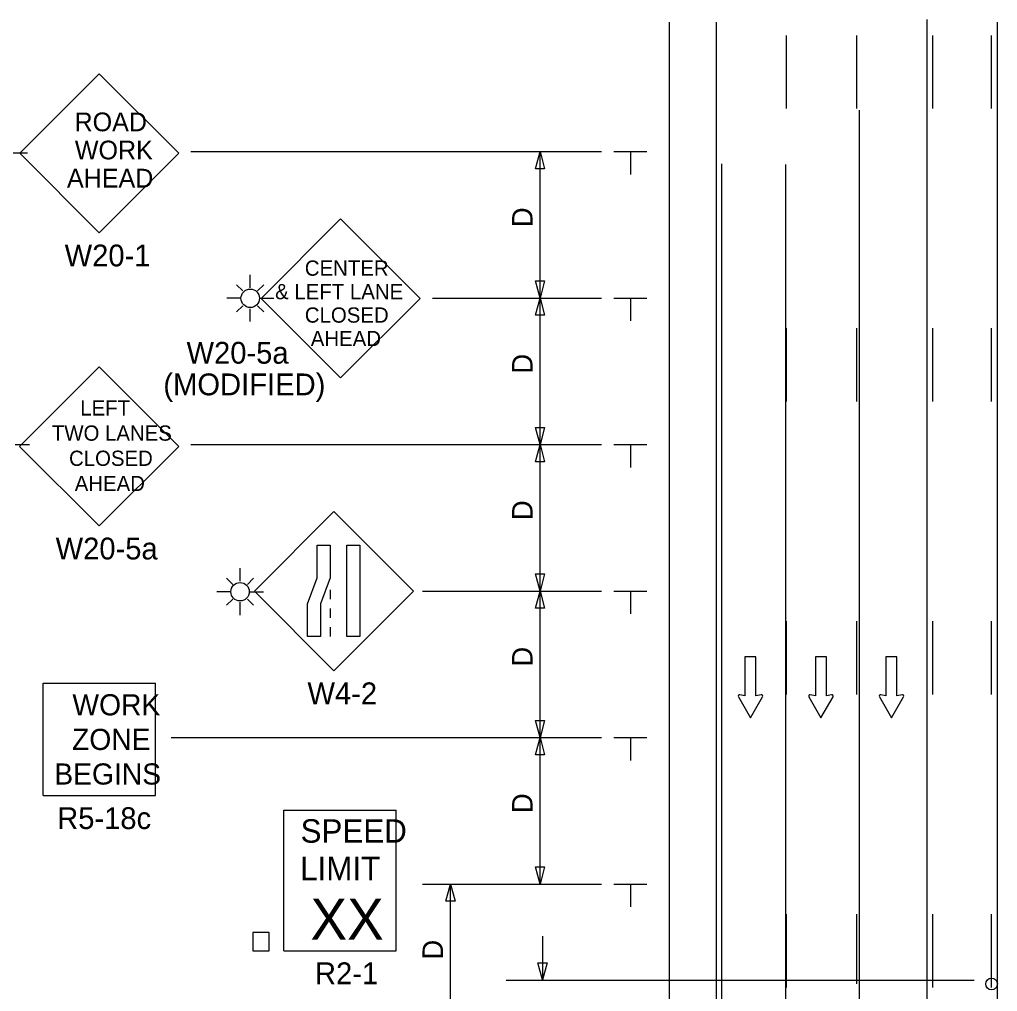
# Model space of a CAD drawing. Extents: x 16038 to 19504, y 5920 to 8321.
# Drawn here: x 16748.5 to 17082.4, y 7879.9 to 8211.6 of the extents above; entities that cross this region are included whole.
import ezdxf

# ---------------------------------------------------------------- set-up
doc = ezdxf.new("R2010")
doc.units = 0
for name, color, linetype in [('ALI_LEGAL_EX', 7, 'Continuous'), ('MT_SCRATCH_LEVEL_E', 7, 'Continuous'), ('PAVT_EDGE_EX', 7, 'Continuous'), ('TRAFFIC_SIGNS_PR', 7, 'Continuous'), ('TYPICAL_TEXT_DIMEN_PR', 7, 'Continuous')]:
    doc.layers.add(name, color=color, linetype=linetype)

msp = doc.modelspace()

# ---------------------------------------------------------------- linework, layer by layer
at = {"layer": 'ALI_LEGAL_EX'}
for points in [[(17010.3, 8181.21), (17010.3, 8206.21)], [(17034.3, 8181.21), (17034.3, 8206.21)], [(17060.3, 8181.21), (17060.3, 8206.21)], [(17080.3, 8181.21), (17080.3, 8206.21)], [(17010.3, 8081.21), (17010.3, 8106.21)], [(17034.3, 8081.21), (17034.3, 8106.21)], [(17060.3, 8081.21), (17060.3, 8106.21)], [(17080.3, 8081.21), (17080.3, 8106.21)], [(17010.3, 7981.21), (17010.3, 8006.21)], [(17034.3, 7981.21), (17034.3, 8006.21)], [(17060.3, 7981.21), (17060.3, 8006.21)], [(17080.3, 7981.21), (17080.3, 8006.21)], [(17010.3, 7881.21), (17010.3, 7906.21)], [(17034.3, 7882.43), (17034.3, 7906.21)], [(17060.3, 7881.21), (17060.3, 7906.21)], [(17080.3, 7881.21), (17080.3, 7906.21)]]:
    msp.add_lwpolyline(points, dxfattribs=at)
at = {"layer": 'MT_SCRATCH_LEVEL_E'}
for p, q in [((16999.9, 7994.07), (16996.16, 7994.07)), ((16996.16, 7994.07), (16996.16, 7980.81)), ((16999.9, 7994.07), (16996.16, 7994.07)), ((16996.16, 7994.07), (16996.16, 7980.81)), ((16999.9, 7980.81), (16999.9, 7994.07)), ((16999.9, 7980.81), (16999.9, 7994.07)), ((17023.97, 7994.07), (17020.23, 7994.07)), ((17020.23, 7994.07), (17020.23, 7980.81)), ((17023.97, 7994.07), (17020.23, 7994.07)), ((17020.23, 7994.07), (17020.23, 7980.81)), ((17023.97, 7994.07), (17020.23, 7994.07)), ((17020.23, 7994.07), (17020.23, 7980.81)), ((17023.97, 7994.07), (17020.23, 7994.07)), ((17020.23, 7994.07), (17020.23, 7980.81)), ((17023.97, 7980.81), (17023.97, 7994.07)), ((17023.97, 7980.81), (17023.97, 7994.07)), ((17023.97, 7980.81), (17023.97, 7994.07)), ((17023.97, 7980.81), (17023.97, 7994.07)), ((17048.04, 7994.07), (17044.3, 7994.07)), ((17044.3, 7994.07), (17044.3, 7980.81)), ((17048.04, 7994.07), (17044.3, 7994.07)), ((17044.3, 7994.07), (17044.3, 7980.81)), ((17048.04, 7994.07), (17044.3, 7994.07)), ((17044.3, 7994.07), (17044.3, 7980.81)), ((17048.04, 7994.07), (17044.3, 7994.07)), ((17044.3, 7994.07), (17044.3, 7980.81)), ((17048.04, 7980.81), (17048.04, 7994.07)), ((17048.04, 7980.81), (17048.04, 7994.07)), ((17048.04, 7980.81), (17048.04, 7994.07)), ((17048.04, 7980.81), (17048.04, 7994.07)), ((16993.9, 7980.44), (16998.05, 7973.2)), ((16993.9, 7980.44), (16998.05, 7973.2)), ((16996.16, 7980.81), (16994.38, 7981.12)), ((16996.16, 7980.81), (16994.38, 7981.12)), ((16998.05, 7973.2), (17002.16, 7980.44)), ((16998.05, 7973.2), (17002.16, 7980.44)), ((17001.68, 7981.12), (16999.9, 7980.81)), ((17001.68, 7981.12), (16999.9, 7980.81)), ((17017.97, 7980.44), (17022.12, 7973.2)), ((17017.97, 7980.44), (17022.12, 7973.2)), ((17017.97, 7980.44), (17022.12, 7973.2)), ((17017.97, 7980.44), (17022.12, 7973.2)), ((17020.23, 7980.81), (17018.45, 7981.12)), ((17020.23, 7980.81), (17018.45, 7981.12)), ((17020.23, 7980.81), (17018.45, 7981.12)), ((17020.23, 7980.81), (17018.45, 7981.12)), ((17022.12, 7973.2), (17026.23, 7980.44)), ((17022.12, 7973.2), (17026.23, 7980.44)), ((17022.12, 7973.2), (17026.23, 7980.44)), ((17022.12, 7973.2), (17026.23, 7980.44)), ((17025.75, 7981.12), (17023.97, 7980.81)), ((17025.75, 7981.12), (17023.97, 7980.81)), ((17025.75, 7981.12), (17023.97, 7980.81)), ((17025.75, 7981.12), (17023.97, 7980.81)), ((17042.04, 7980.44), (17046.19, 7973.2)), ((17042.04, 7980.44), (17046.19, 7973.2)), ((17042.04, 7980.44), (17046.19, 7973.2)), ((17042.04, 7980.44), (17046.19, 7973.2)), ((17044.3, 7980.81), (17042.52, 7981.12)), ((17044.3, 7980.81), (17042.52, 7981.12)), ((17044.3, 7980.81), (17042.52, 7981.12)), ((17044.3, 7980.81), (17042.52, 7981.12)), ((17046.19, 7973.2), (17050.3, 7980.44)), ((17046.19, 7973.2), (17050.3, 7980.44)), ((17046.19, 7973.2), (17050.3, 7980.44)), ((17046.19, 7973.2), (17050.3, 7980.44)), ((17049.82, 7981.12), (17048.04, 7980.81)), ((17049.82, 7981.12), (17048.04, 7980.81)), ((17049.82, 7981.12), (17048.04, 7980.81)), ((17049.82, 7981.12), (17048.04, 7980.81))]:
    msp.add_line(p, q, dxfattribs=at)
for centre, start, end in [((16994.31, 7980.67), 80.0362, 209.7731), ((16994.31, 7980.67), 80.0362, 209.7731), ((17001.75, 7980.67), 330.4248, 99.9638), ((17001.75, 7980.67), 330.4248, 99.9638), ((17018.38, 7980.67), 80.0362, 209.7731), ((17018.38, 7980.67), 80.0362, 209.7731), ((17018.38, 7980.67), 80.0362, 209.7731), ((17018.38, 7980.67), 80.0362, 209.7731), ((17025.82, 7980.67), 330.4248, 99.9638), ((17025.82, 7980.67), 330.4248, 99.9638), ((17025.82, 7980.67), 330.4248, 99.9638), ((17025.82, 7980.67), 330.4248, 99.9638), ((17042.45, 7980.67), 80.0362, 209.7731), ((17042.45, 7980.67), 80.0362, 209.7731), ((17042.45, 7980.67), 80.0362, 209.7731), ((17042.45, 7980.67), 80.0362, 209.7731), ((17049.89, 7980.67), 330.4248, 99.9638), ((17049.89, 7980.67), 330.4248, 99.9638), ((17049.89, 7980.67), 330.4248, 99.9638), ((17049.89, 7980.67), 330.4248, 99.9638)]:
    msp.add_arc(centre, 0.463, start, end, dxfattribs=at)
at = {"layer": 'PAVT_EDGE_EX'}
for p, q in [((16970.3, 8210.68), (16970.3, 7367.79)), ((16986.3, 8210.68), (16986.3, 7368.22)), ((17058.3, 8211.6), (17058.3, 7768.24)), ((17082.3, 8210.68), (17082.3, 7784.85)), ((17035.15, 8180.7), (17035.15, 7351.51)), ((16988.15, 8162.34), (16988.15, 7333.15)), ((17010.01, 8162.15), (17010.01, 7332.97)), ((17058.3, 8068.76), (17058.3, 7795.75)), ((17082.3, 8068.76), (17082.3, 7826.61))]:
    msp.add_line(p, q, dxfattribs=at)
at = {"layer": 'TRAFFIC_SIGNS_PR'}
for p, q in [((16775.73, 8193.09), (16748.58, 8165.94)), ((16802.88, 8165.94), (16775.73, 8193.09)), ((16746.28, 8166.09), (16751.17, 8166.09)), ((16748.58, 8165.94), (16775.73, 8138.79)), ((16775.73, 8138.79), (16802.88, 8165.94)), ((16858.11, 8143.59), (16830.96, 8116.43)), ((16858.11, 8143.59), (16830.96, 8116.43)), ((16885.27, 8116.43), (16858.11, 8143.59)), ((16885.27, 8116.43), (16858.11, 8143.59)), ((16827.25, 8120), (16827.25, 8124.51)), ((16824.73, 8118.96), (16822.62, 8121.07)), ((16829.76, 8118.96), (16831.87, 8121.07)), ((16824.09, 8116.45), (16819.25, 8116.45)), ((16830.4, 8116.45), (16835.28, 8116.45)), ((16830.96, 8116.43), (16858.11, 8089.28)), ((16830.96, 8116.43), (16858.11, 8089.28)), ((16858.11, 8089.28), (16885.27, 8116.43)), ((16858.11, 8089.28), (16885.27, 8116.43)), ((16824.73, 8113.94), (16822.62, 8111.83)), ((16827.25, 8108.48), (16827.25, 8112.89)), ((16829.76, 8113.94), (16831.87, 8111.83)), ((16775.68, 8093.06), (16748.53, 8065.91)), ((16802.84, 8065.91), (16775.68, 8093.06)), ((16747.01, 8066.53), (16751.89, 8066.53)), ((16748.53, 8065.91), (16775.68, 8038.76)), ((16775.68, 8038.76), (16802.84, 8065.91)), ((16855.84, 8043.65), (16828.69, 8016.5)), ((16883, 8016.5), (16855.84, 8043.65)), ((16823.8, 8019.85), (16823.8, 8024.35)), ((16821.28, 8018.81), (16819.18, 8020.91)), ((16826.31, 8018.81), (16828.42, 8020.91)), ((16820.64, 8016.29), (16815.81, 8016.29)), ((16826.95, 8016.29), (16831.83, 8016.29)), ((16828.69, 8016.5), (16855.84, 7989.34)), ((16854.6, 8016.99), (16854.6, 8013.79)), ((16855.84, 7989.34), (16883, 8016.5)), ((16821.28, 8013.78), (16819.18, 8011.67)), ((16823.8, 8008.33), (16823.8, 8012.74)), ((16826.31, 8013.78), (16828.42, 8011.67)), ((16854.6, 8010.59), (16854.6, 8007.39)), ((16854.6, 8004.19), (16854.6, 8000.99)), ((16756.54, 7946.73), (16756.54, 7985.13)), ((16756.54, 7985.13), (16794.94, 7985.13)), ((16794.94, 7946.73), (16794.94, 7985.13)), ((16756.54, 7946.73), (16794.94, 7946.73)), ((16838.69, 7941.78), (16877.1, 7941.78)), ((16838.69, 7893.78), (16838.69, 7941.78)), ((16877.1, 7893.78), (16877.1, 7941.78)), ((16838.69, 7893.78), (16877.1, 7893.78))]:
    msp.add_line(p, q, dxfattribs=at)
for points in [[(16854.6, 8032.23), (16854.6, 8021.05), (16851.25, 8012.17), (16851.25, 8000.99), (16846.76, 8000.99), (16846.76, 8012.17), (16850.1, 8021.05), (16850.1, 8032.23)], [(16864.73, 8032.23), (16864.73, 8000.99), (16860.24, 8000.99), (16860.24, 8032.23)], [(16828.09, 7893.78), (16833.68, 7893.78), (16833.68, 7899.95), (16828.09, 7899.95)]]:
    msp.add_lwpolyline(points, close=True, dxfattribs=at)
for centre, radius in [((16827.25, 8116.45), 3.15), ((16823.8, 8016.29), 3.15), ((17080.36, 7882.42), 2)]:
    msp.add_circle(centre, radius, dxfattribs=at)
at = {"layer": 'TYPICAL_TEXT_DIMEN_PR'}
for p, q in [((16806.97, 8166.51), (16947.2, 8166.51)), ((16924.63, 8160.65), (16926.2, 8166.51)), ((16924.63, 8160.65), (16926.2, 8166.51)), ((16926.2, 8116.51), (16926.2, 8166.51)), ((16926.2, 8166.51), (16927.77, 8160.65)), ((16926.2, 8116.51), (16926.2, 8166.51)), ((16926.2, 8166.51), (16927.77, 8160.65)), ((16951.45, 8166.51), (16962.7, 8166.51)), ((16951.45, 8166.51), (16962.7, 8166.51)), ((16957.08, 8166.51), (16957.08, 8158.72)), ((16957.08, 8166.51), (16957.08, 8158.72)), ((16926.2, 8160.65), (16924.63, 8160.65)), ((16926.2, 8160.65), (16924.63, 8160.65)), ((16927.77, 8160.65), (16926.2, 8160.65)), ((16927.77, 8160.65), (16926.2, 8160.65)), ((16926.2, 8116.51), (16924.63, 8122.37)), ((16924.63, 8122.37), (16926.2, 8122.37)), ((16926.2, 8116.51), (16924.63, 8122.37)), ((16924.63, 8122.37), (16926.2, 8122.37)), ((16926.2, 8122.37), (16927.77, 8122.37)), ((16927.77, 8122.37), (16926.2, 8116.51)), ((16926.2, 8122.37), (16927.77, 8122.37)), ((16927.77, 8122.37), (16926.2, 8116.51)), ((16889.48, 8116.51), (16947.2, 8116.51)), ((16904.5, 8116.51), (16947.2, 8116.51)), ((16907.56, 8116.51), (16947.2, 8116.51)), ((16924.63, 8110.65), (16926.2, 8116.51)), ((16924.63, 8110.65), (16926.2, 8116.51)), ((16926.2, 8116.51), (16927.77, 8110.65)), ((16926.2, 8116.51), (16927.77, 8110.65)), ((16926.2, 8066.51), (16926.2, 8116.51)), ((16951.45, 8116.51), (16962.7, 8116.51)), ((16951.45, 8116.51), (16962.7, 8116.51)), ((16957.08, 8116.51), (16957.08, 8108.72)), ((16957.08, 8116.51), (16957.08, 8108.72)), ((16926.2, 8110.65), (16924.63, 8110.65)), ((16926.2, 8110.65), (16924.63, 8110.65)), ((16927.77, 8110.65), (16926.2, 8110.65)), ((16927.77, 8110.65), (16926.2, 8110.65)), ((16926.2, 8066.51), (16924.63, 8072.37)), ((16924.63, 8072.37), (16926.2, 8072.37)), ((16926.2, 8066.51), (16924.63, 8072.37)), ((16924.63, 8072.37), (16926.2, 8072.37)), ((16926.2, 8072.37), (16927.77, 8072.37)), ((16927.77, 8072.37), (16926.2, 8066.51)), ((16926.2, 8072.37), (16927.77, 8072.37)), ((16927.77, 8072.37), (16926.2, 8066.51)), ((16806.97, 8066.51), (16947.2, 8066.51)), ((16806.97, 8066.51), (16947.2, 8066.51)), ((16924.63, 8060.65), (16926.2, 8066.51)), ((16924.63, 8060.65), (16926.2, 8066.51)), ((16926.2, 8066.51), (16927.77, 8060.65)), ((16926.2, 8016.51), (16926.2, 8066.51)), ((16926.2, 8066.51), (16927.77, 8060.65)), ((16926.2, 8016.51), (16926.2, 8066.51)), ((16951.45, 8066.51), (16962.7, 8066.51)), ((16957.08, 8066.51), (16957.08, 8058.72)), ((16926.2, 8060.65), (16924.63, 8060.65)), ((16926.2, 8060.65), (16924.63, 8060.65)), ((16927.77, 8060.65), (16926.2, 8060.65)), ((16927.77, 8060.65), (16926.2, 8060.65)), ((16926.2, 8016.51), (16924.63, 8022.37)), ((16924.63, 8022.37), (16926.2, 8022.37)), ((16926.2, 8016.51), (16924.63, 8022.37)), ((16924.63, 8022.37), (16926.2, 8022.37)), ((16926.2, 8022.37), (16927.77, 8022.37)), ((16927.77, 8022.37), (16926.2, 8016.51)), ((16926.2, 8022.37), (16927.77, 8022.37)), ((16927.77, 8022.37), (16926.2, 8016.51)), ((16886.11, 8016.51), (16947.2, 8016.51)), ((16924.63, 8010.65), (16926.2, 8016.51)), ((16926.2, 7966.51), (16926.2, 8016.51)), ((16926.2, 8016.51), (16927.77, 8010.65)), ((16951.45, 8016.51), (16962.7, 8016.51)), ((16957.08, 8016.51), (16957.08, 8008.72)), ((16926.2, 8010.65), (16924.63, 8010.65)), ((16927.77, 8010.65), (16926.2, 8010.65)), ((16926.2, 7966.51), (16924.63, 7972.37)), ((16924.63, 7972.37), (16926.2, 7972.37)), ((16926.2, 7966.51), (16924.63, 7972.37)), ((16924.63, 7972.37), (16926.2, 7972.37)), ((16926.2, 7972.37), (16927.77, 7972.37)), ((16927.77, 7972.37), (16926.2, 7966.51)), ((16926.2, 7972.37), (16927.77, 7972.37)), ((16927.77, 7972.37), (16926.2, 7966.51)), ((16800.3, 7966.51), (16947.2, 7966.51)), ((16802.79, 7966.51), (16947.2, 7966.51)), ((16924.63, 7960.65), (16926.2, 7966.51)), ((16924.63, 7960.65), (16926.2, 7966.51)), ((16926.2, 7966.51), (16927.77, 7960.65)), ((16926.2, 7916.51), (16926.2, 7966.51)), ((16926.2, 7966.51), (16927.77, 7960.65)), ((16926.2, 7916.51), (16926.2, 7966.51)), ((16951.45, 7966.51), (16962.7, 7966.51)), ((16957.08, 7966.51), (16957.08, 7958.72)), ((16926.2, 7960.65), (16924.63, 7960.65)), ((16926.2, 7960.65), (16924.63, 7960.65)), ((16927.77, 7960.65), (16926.2, 7960.65)), ((16927.77, 7960.65), (16926.2, 7960.65)), ((16926.2, 7916.51), (16924.63, 7922.37)), ((16924.63, 7922.37), (16926.2, 7922.37)), ((16926.2, 7916.51), (16924.63, 7922.37)), ((16924.63, 7922.37), (16926.2, 7922.37)), ((16926.2, 7922.37), (16927.77, 7922.37)), ((16927.77, 7922.37), (16926.2, 7916.51)), ((16926.2, 7922.37), (16927.77, 7922.37)), ((16927.77, 7922.37), (16926.2, 7916.51)), ((16886.11, 7916.51), (16947.2, 7916.51)), ((16894.05, 7910.65), (16895.62, 7916.51)), ((16895.62, 7916.51), (16897.19, 7910.65)), ((16895.62, 7866.51), (16895.62, 7916.51)), ((16951.45, 7916.51), (16962.7, 7916.51)), ((16957.08, 7916.51), (16957.08, 7908.72)), ((16895.62, 7910.65), (16894.05, 7910.65)), ((16897.19, 7910.65), (16895.62, 7910.65)), ((16927.06, 7898.69), (16927.06, 7883.77)), ((16927.02, 7883.79), (16925.45, 7889.65)), ((16925.45, 7889.65), (16927.02, 7889.65)), ((16927.02, 7889.65), (16928.59, 7889.65)), ((16928.59, 7889.65), (16927.02, 7883.79)), ((16914.64, 7883.75), (17074.37, 7883.75))]:
    msp.add_line(p, q, dxfattribs=at)

# ---------------------------------------------------------------- texts
at = {"layer": 'TRAFFIC_SIGNS_PR'}
for s, height, p in [('ROAD', 6.4, (16767.27, 8173.47)), ('WORK', 6.4, (16767.38, 8163.87)), ('AHEAD', 6.4, (16764.69, 8154.27)), ('W20-1', 7.44, (16763.9, 8127.35))]:
    msp.add_text(s, height=height, rotation=360, dxfattribs=at).set_placement(p)
for s, height, p in [('CENTER', 5.206, (16845.89, 8124.16)), ('& LEFT LANE', 5.2065, (16835.75, 8116.15)), ('CLOSED', 5.206, (16845.9, 8108.14)), ('AHEAD', 5.206, (16847.92, 8100.13)), ('W20-5a', 7.44, (16805.52, 8094.14)), ('(MODIFIED)', 7.449, (16797.59, 8083.35)), ('LEFT', 5.2, (16769.22, 8076.45)), ('TWO LANES', 5.2, (16759.54, 8067.85)), ('CLOSED', 5.2, (16765.4, 8059.25)), ('AHEAD', 5.2, (16767.34, 8050.65)), ('W20-5a', 7.44, (16760.82, 8027.32)), ('W4-2', 7.44, (16846.8, 7977.9)), ('WORK', 7.217, (16766.54, 7974.1)), ('ZONE', 7.217, (16766.42, 7962.29)), ('BEGINS', 7.217, (16760.35, 7950.48)), ('R5-18c', 7.44, (16761.35, 7935.29)), ('SPEED', 8, (16844.46, 7930.64)), ('LIMIT', 8, (16844.3, 7917.84)), ('XX', 14.031, (16847.81, 7897.54)), ('R2-1', 7.44, (16849.37, 7882.34))]:
    msp.add_text(s, height=height, dxfattribs=at).set_placement(p)
at = {"layer": 'TYPICAL_TEXT_DIMEN_PR'}
for p in [(16923.64, 8140.73), (16923.64, 8140.73), (16923.64, 8090.73), (16923.64, 8090.73), (16923.64, 8040.73), (16923.64, 8040.73), (16923.64, 7990.73), (16923.64, 7990.73), (16923.64, 7940.73), (16923.64, 7940.73), (16893.06, 7890.73)]:
    msp.add_text('D', height=7, rotation=90, dxfattribs=at).set_placement(p)

doc.saveas('drawing.dxf')
